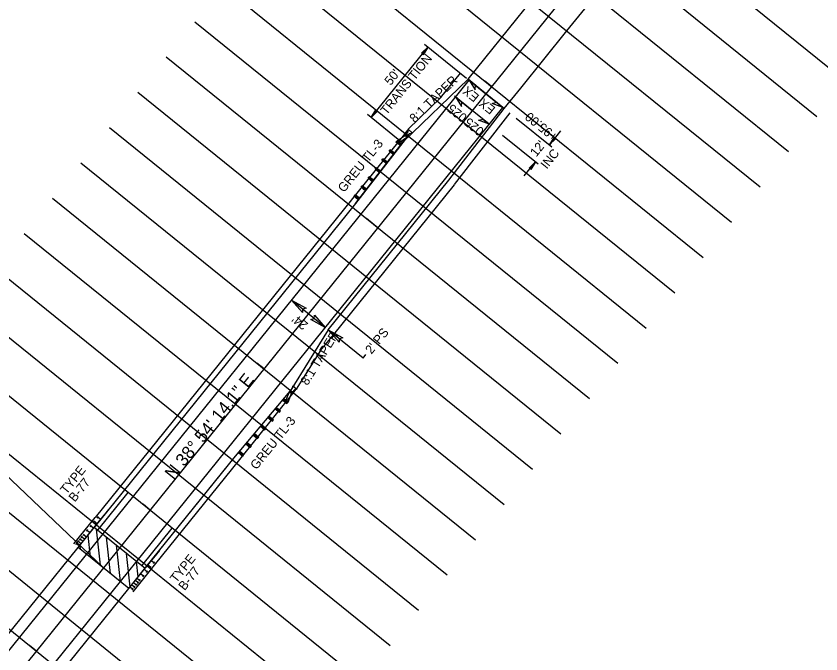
# Model space of a CAD drawing. Extents: x 2292992 to 2295123, y 892701 to 896230.
# Drawn here: x 2293899.6 to 2294343.7, y 893581.3 to 893933 of the extents above; entities that cross this region are included whole.
import ezdxf

# ---------------------------------------------------------------- set-up
doc = ezdxf.new("R2010")
doc.units = 0
for name, color, linetype in [('Default', 7, 'Continuous'), ('Prop Approach Slab', 7, 'Continuous'), ('Prop Approach Slab Hatching', 7, 'Continuous'), ('Prop Conc Shoulder Berm Gutter', 7, 'Continuous'), ('Prop Dimension', 7, 'Continuous'), ('Prop Dimension Text', 7, 'Continuous'), ('Prop EOT', 7, 'Continuous'), ('Prop Guardrail', 7, 'Continuous'), ('Prop Guardrail Anchor Unit CELL', 7, 'Continuous'), ('Prop Horizontal Alignment', 7, 'Continuous'), ('Prop Horizontal Alignment Direction Label', 7, 'Continuous'), ('Prop Horizontal Alignment Tick Large', 7, 'Continuous'), ('Prop Horizontal Alignment Tick Small', 7, 'Continuous'), ('Prop Paved Shoulder', 7, 'Continuous'), ('Prop Roadway Bridge', 7, 'Continuous'), ('Prop SBG', 7, 'Continuous'), ('Prop Structure Anchor Unit CELL', 7, 'Continuous'), ('Prop Superelevation  Arrow CELL', 7, 'Continuous'), ('Prop Superelevation Label', 7, 'Continuous'), ('Prop Terminator CELL', 7, 'Continuous'), ('Scratch_Level_0', 7, 'Continuous'), ('Scratch_Level_3', 7, 'Continuous'), ('Scratch_Level_4', 7, 'Continuous'), ('Scratch_Level_5', 7, 'Continuous'), ('Typical Terminator CELL', 7, 'Continuous')]:
    doc.layers.add(name, color=color, linetype=linetype)

# ---------------------------------------------------------------- blocks, each defined once
blk = doc.blocks.new('TERMINATOR')
at = {"layer": 'Typical Terminator CELL'}
blk.add_lwpolyline([(-0.469, 0.081), (0, 0), (-0.471, -0.083), (-0.411, 0)], close=True, dxfattribs=at)

msp = doc.modelspace()

# ---------------------------------------------------------------- linework, layer by layer
at = {"layer": 'Default'}
for p, q in [((2294158.83, 893890.22), (2294148.96, 893898.19)), ((2294151.29, 893880.88), (2294141.42, 893888.85)), ((2294158.83, 893890.22), (2294168.95, 893882.05))]:
    msp.add_line(p, q, dxfattribs=at)
at = {"layer": 'Prop Approach Slab'}
for p, q in [((2293933.81, 893640.05), (2293943.23, 893651.72)), ((2293970.72, 893628.47), (2293942.71, 893651.08)), ((2293961.82, 893617.44), (2293971.24, 893629.11))]:
    msp.add_line(p, q, dxfattribs=at)
at = {"layer": 'Prop Approach Slab Hatching'}
for p, q in [((2293946.08, 893630.14), (2293943.96, 893650.07)), ((2293940.58, 893634.58), (2293939.27, 893646.82)), ((2293951.59, 893625.7), (2293949.46, 893645.63)), ((2293935.08, 893639.03), (2293934.83, 893641.32)), ((2293957.09, 893621.26), (2293954.96, 893641.19)), ((2293962.44, 893618.21), (2293960.46, 893636.75)), ((2293966.88, 893623.71), (2293965.97, 893632.31))]:
    msp.add_line(p, q, dxfattribs=at)
at = {"layer": 'Prop Conc Shoulder Berm Gutter'}
for p, q in [((2293950.62, 893660.88), (2293943.23, 893651.74)), ((2293978.62, 893638.26), (2293971.24, 893629.12))]:
    msp.add_line(p, q, dxfattribs=at)
at = {"layer": 'Prop Dimension'}
for p, q in [((2294095.46, 893877.11), (2294126.86, 893916.02)), ((2294124.91, 893917.6), (2294148.18, 893898.82)), ((2294112.45, 893863.4), (2294093.5, 893878.69)), ((2294175.59, 893876.7), (2294195.14, 893860.92)), ((2294168.05, 893867.36), (2294187.6, 893851.58)), ((2294200.05, 893869.8), (2294193.81, 893862.07)), ((2294179.96, 893844.91), (2294186.19, 893852.64)), ((2294070.18, 893761.26), (2294051.5, 893776.33)), ((2294091.05, 893744.42), (2294071.74, 893760.01)), ((2294091.05, 893744.42), (2294092.62, 893746.37))]:
    msp.add_line(p, q, dxfattribs=at)
at = {"layer": 'Prop Dimension Text'}
msp.add_line((2293783.81, 893784.73), (2293947.82, 893628.75), dxfattribs=at)
at = {"layer": 'Prop EOT'}
for p, q in [((2293677.44, 893312.82), (2294149.49, 893897.76)), ((2294168.17, 893882.69), (2294149.49, 893897.76)), ((2293696.11, 893297.74), (2294168.17, 893882.69))]:
    msp.add_line(p, q, dxfattribs=at)
for points in [[(2294148.97, 893898.17), (2294158.28, 893909.61), (2294184.27, 893942.27), (2294211.74, 893976.09), (2294233.52, 894003.42)], [(2294168.97, 893882.04), (2294178.04, 893893.2), (2294203.54, 893924.89), (2294231.52, 893959.52), (2294253.69, 893987.15)]]:
    msp.add_lwpolyline(points, dxfattribs=at)
at = {"layer": 'Prop Guardrail'}
for p, q in [((2294086.89, 893829.74), (2293945.58, 893654.64)), ((2293973.6, 893632.03), (2294020.7, 893690.4))]:
    msp.add_line(p, q, dxfattribs=at)
at = {"layer": 'Prop Guardrail Anchor Unit CELL'}
for p, q in [((2294086.89, 893829.74), (2294115.51, 893866.7)), ((2294109.79, 893864.3), (2294114.02, 893867.22)), ((2294114.02, 893867.22), (2294114.63, 893868.01)), ((2294114.02, 893867.22), (2294114.33, 893867.62)), ((2294115.21, 893866.3), (2294114.02, 893867.22)), ((2294115.82, 893867.09), (2294114.02, 893867.22)), ((2294115.8, 893869.13), (2294114.52, 893867.53)), ((2294114.52, 893867.53), (2294115, 893867.15)), ((2294115.82, 893867.09), (2294114.63, 893868.01)), ((2294114.63, 893868.01), (2294115.21, 893866.3)), ((2294115, 893867.15), (2294115.47, 893866.77)), ((2294115.47, 893866.77), (2294116.76, 893868.37)), ((2294115.87, 893870.59), (2294115.8, 893869.13)), ((2294118.17, 893868.74), (2294115.87, 893870.59)), ((2294116.76, 893868.37), (2294118.17, 893868.74)), ((2294109.17, 893863.51), (2294109.79, 893864.3)), ((2294111.59, 893861.64), (2294109.17, 893863.51)), ((2294111, 893863.37), (2294109.17, 893863.51)), ((2294112.21, 893862.43), (2294109.79, 893864.3)), ((2294109.79, 893864.3), (2294110.38, 893862.58)), ((2294110.38, 893862.58), (2294111, 893863.37)), ((2294110.38, 893862.58), (2294112.21, 893862.43)), ((2294111, 893863.37), (2294115.21, 893866.3)), ((2294111.59, 893861.64), (2294111, 893863.37)), ((2294105.36, 893858.49), (2294105.98, 893859.28)), ((2294107.74, 893856.66), (2294105.36, 893858.49)), ((2294107.16, 893858.36), (2294105.36, 893858.49)), ((2294108.35, 893857.45), (2294105.98, 893859.28)), ((2294105.98, 893859.28), (2294106.55, 893857.57)), ((2294106.55, 893857.57), (2294107.16, 893858.36)), ((2294107.74, 893856.66), (2294107.16, 893858.36)), ((2294101.4, 893853.59), (2294102.01, 893854.39)), ((2294103.88, 893851.67), (2294101.4, 893853.59)), ((2294103.25, 893853.42), (2294101.4, 893853.59)), ((2294104.49, 893852.46), (2294102.01, 893854.39)), ((2294102.01, 893854.39), (2294102.64, 893852.63)), ((2294102.64, 893852.63), (2294103.25, 893853.42)), ((2294103.88, 893851.67), (2294103.25, 893853.42)), ((2294106.55, 893857.57), (2294108.35, 893857.45)), ((2294097.62, 893848.55), (2294098.23, 893849.34)), ((2294100.63, 893847.48), (2294098.23, 893849.34)), ((2294098.23, 893849.34), (2294098.82, 893847.62)), ((2294102.64, 893852.63), (2294104.49, 893852.46)), ((2294100.02, 893846.69), (2294097.62, 893848.55)), ((2294099.43, 893848.41), (2294097.62, 893848.55)), ((2294098.82, 893847.62), (2294099.43, 893848.41)), ((2294098.82, 893847.62), (2294100.63, 893847.48)), ((2294100.02, 893846.69), (2294099.43, 893848.41)), ((2294100.02, 893846.69), (2294100.63, 893847.48)), ((2294093.75, 893843.58), (2294094.36, 893844.37)), ((2294096.16, 893841.71), (2294093.75, 893843.58)), ((2294095.57, 893843.43), (2294093.75, 893843.58)), ((2294096.77, 893842.5), (2294094.36, 893844.37)), ((2294094.36, 893844.37), (2294094.96, 893842.64)), ((2294094.96, 893842.64), (2294095.57, 893843.43)), ((2294094.96, 893842.64), (2294096.77, 893842.5)), ((2294096.16, 893841.71), (2294095.57, 893843.43)), ((2294089.89, 893838.6), (2294090.5, 893839.39)), ((2294092.3, 893836.73), (2294089.89, 893838.6)), ((2294091.71, 893838.45), (2294089.89, 893838.6)), ((2294092.92, 893837.52), (2294090.5, 893839.39)), ((2294090.5, 893839.39), (2294091.1, 893837.66)), ((2294091.1, 893837.66), (2294091.71, 893838.45)), ((2294091.1, 893837.66), (2294092.92, 893837.52)), ((2294092.3, 893836.73), (2294091.71, 893838.45)), ((2294086.07, 893833.58), (2294086.69, 893834.37)), ((2294088.44, 893831.75), (2294086.07, 893833.58)), ((2294087.87, 893833.46), (2294086.07, 893833.58)), ((2294089.06, 893832.54), (2294086.69, 893834.37)), ((2294086.69, 893834.37), (2294087.26, 893832.67)), ((2294087.26, 893832.67), (2294087.87, 893833.46)), ((2294087.26, 893832.67), (2294089.06, 893832.54)), ((2294089.06, 893832.54), (2294087.87, 893833.46)), ((2294087.87, 893833.46), (2294088.44, 893831.75)), ((2294088.44, 893831.75), (2294089.06, 893832.54)), ((2294052.15, 893727.75), (2294052.22, 893729.21)), ((2294052.22, 893729.21), (2294054.51, 893727.36)), ((2294020.7, 893690.4), (2294050.78, 893726.19)), ((2294048.48, 893721.07), (2294050.46, 893725.8)), ((2294049.65, 893720.08), (2294051.61, 893724.84)), ((2294050.46, 893725.8), (2294051.61, 893724.84)), ((2294052.25, 893725.6), (2294050.46, 893725.8)), ((2294050.86, 893726.16), (2294052.15, 893727.75)), ((2294051.34, 893725.78), (2294050.86, 893726.16)), ((2294051.1, 893726.57), (2294052.25, 893725.6)), ((2294051.1, 893726.57), (2294051.61, 893724.84)), ((2294051.81, 893725.39), (2294051.34, 893725.78)), ((2294051.61, 893724.84), (2294052.25, 893725.6)), ((2294051.61, 893724.84), (2294051.93, 893725.22)), ((2294053.1, 893726.98), (2294051.81, 893725.39)), ((2294054.51, 893727.36), (2294053.1, 893726.98)), ((2294046.66, 893721.29), (2294049.01, 893719.31)), ((2294046.66, 893721.29), (2294048.48, 893721.07)), ((2294047.31, 893722.05), (2294049.65, 893720.08)), ((2294047.84, 893720.3), (2294047.31, 893722.05)), ((2294047.84, 893720.3), (2294048.48, 893721.07)), ((2294049.65, 893720.08), (2294047.84, 893720.3)), ((2294048.48, 893721.07), (2294049.01, 893719.31)), ((2294042.61, 893716.46), (2294044.91, 893714.53)), ((2294042.61, 893716.46), (2294044.4, 893716.26)), ((2294043.25, 893717.23), (2294045.55, 893715.3)), ((2294043.76, 893715.5), (2294043.25, 893717.23)), ((2294043.76, 893715.5), (2294044.4, 893716.26)), ((2294044.4, 893716.26), (2294044.91, 893714.53)), ((2294049.01, 893719.31), (2294049.65, 893720.08)), ((2294038.55, 893711.64), (2294040.96, 893709.62)), ((2294038.55, 893711.64), (2294040.4, 893711.39)), ((2294039.2, 893712.4), (2294041.6, 893710.38)), ((2294039.75, 893710.63), (2294039.2, 893712.4)), ((2294039.75, 893710.63), (2294040.4, 893711.39)), ((2294040.4, 893711.39), (2294040.96, 893709.62)), ((2294045.55, 893715.3), (2294043.76, 893715.5)), ((2294044.91, 893714.53), (2294045.55, 893715.3)), ((2294034.5, 893706.81), (2294035.14, 893707.58)), ((2294034.5, 893706.81), (2294036.82, 893704.86)), ((2294034.5, 893706.81), (2294036.31, 893706.6)), ((2294035.14, 893707.58), (2294037.47, 893705.63)), ((2294035.66, 893705.84), (2294035.14, 893707.58)), ((2294041.6, 893710.38), (2294039.75, 893710.63)), ((2294040.96, 893709.62), (2294041.6, 893710.38)), ((2294031.09, 893702.76), (2294033.42, 893700.8)), ((2294031.61, 893701.01), (2294031.09, 893702.76)), ((2294035.66, 893705.84), (2294036.31, 893706.6)), ((2294037.47, 893705.63), (2294035.66, 893705.84)), ((2294036.31, 893706.6), (2294036.82, 893704.86)), ((2294036.82, 893704.86), (2294037.47, 893705.63)), ((2294027.03, 893697.93), (2294029.37, 893695.97)), ((2294027.56, 893696.19), (2294027.03, 893697.93)), ((2294030.45, 893701.99), (2294032.78, 893700.03)), ((2294030.45, 893701.99), (2294032.26, 893701.78)), ((2294031.61, 893701.01), (2294032.26, 893701.78)), ((2294033.42, 893700.8), (2294031.61, 893701.01)), ((2294032.26, 893701.78), (2294032.78, 893700.03)), ((2294032.78, 893700.03), (2294033.42, 893700.8)), ((2294026.39, 893697.17), (2294028.73, 893695.2)), ((2294026.39, 893697.17), (2294028.2, 893696.95)), ((2294027.56, 893696.19), (2294028.2, 893696.95)), ((2294029.37, 893695.97), (2294027.56, 893696.19)), ((2294028.2, 893696.95), (2294028.73, 893695.2)), ((2294028.73, 893695.2), (2294029.37, 893695.97)), ((2294022.34, 893692.34), (2294022.98, 893693.11)), ((2294022.34, 893692.34), (2294024.63, 893690.41)), ((2294024.13, 893692.14), (2294022.34, 893692.34)), ((2294022.98, 893693.11), (2294025.28, 893691.18)), ((2294022.98, 893693.11), (2294024.13, 893692.14)), ((2294023.48, 893691.38), (2294022.98, 893693.11)), ((2294023.48, 893691.38), (2294024.13, 893692.14)), ((2294025.28, 893691.18), (2294023.48, 893691.38)), ((2294024.13, 893692.14), (2294024.63, 893690.41)), ((2294024.63, 893690.41), (2294025.28, 893691.18))]:
    msp.add_line(p, q, dxfattribs=at)
at = {"layer": 'Prop Horizontal Alignment'}
msp.add_line((2293686.78, 893305.28), (2294292.7, 894056.1), dxfattribs=at)
at = {"layer": 'Prop Horizontal Alignment Tick Large'}
msp.add_line((2294099.17, 893816.29), (2294092.94, 893821.32), dxfattribs=at)
at = {"layer": 'Prop Horizontal Alignment Tick Small'}
for p, q in [((2294161.97, 893894.11), (2294158.08, 893897.25)), ((2294036.37, 893738.47), (2294032.48, 893741.61)), ((2293973.56, 893660.65), (2293969.67, 893663.79)), ((2293910.76, 893582.83), (2293906.87, 893585.97))]:
    msp.add_line(p, q, dxfattribs=at)
at = {"layer": 'Prop Paved Shoulder'}
for p, q in [((2294113.14, 893863.64), (2294148.96, 893898.19)), ((2294148.96, 893898.19), (2294149.49, 893897.76)), ((2294138.32, 893842.52), (2294168.95, 893882.05)), ((2294168.95, 893882.05), (2294168.17, 893882.69)), ((2294086.89, 893829.74), (2294113.14, 893863.64)), ((2294071.74, 893760.01), (2294138.32, 893842.52)), ((2294086.9, 893829.73), (2293945.59, 893654.64)), ((2294071.74, 893760.01), (2294050.78, 893726.19)), ((2294020.7, 893690.4), (2294050.78, 893726.19)), ((2293971.24, 893629.12), (2294020.69, 893690.4)), ((2293943.24, 893651.72), (2293945.59, 893654.64))]:
    msp.add_line(p, q, dxfattribs=at)
at = {"layer": 'Prop Roadway Bridge'}
for p, q in [((2293801.93, 893476.63), (2293933.81, 893640.05)), ((2293933.18, 893639.27), (2293933.18, 893639.27)), ((2293961.82, 893617.44), (2293933.81, 893640.05)), ((2293829.94, 893454.02), (2293961.82, 893617.44))]:
    msp.add_line(p, q, dxfattribs=at)
at = {"layer": 'Prop SBG'}
for p, q in [((2293961.17, 893670.21), (2293944.53, 893649.61)), ((2293968.9, 893629.94), (2293985.6, 893650.62))]:
    msp.add_line(p, q, dxfattribs=at)
at = {"layer": 'Prop Structure Anchor Unit CELL'}
for p, q in [((2293933.81, 893640.05), (2293948.17, 893657.85)), ((2293942.33, 893653.8), (2293943.05, 893654.69)), ((2293944.25, 893652.99), (2293942.69, 893654.24)), ((2293944.3, 893656.23), (2293945.02, 893657.12)), ((2293946.21, 893655.42), (2293944.66, 893656.68)), ((2293938.41, 893648.93), (2293939.13, 893649.83)), ((2293940.32, 893648.12), (2293938.77, 893649.38)), ((2293940.37, 893651.37), (2293941.09, 893652.26)), ((2293942.29, 893650.56), (2293940.73, 893651.81)), ((2293934.48, 893644.07), (2293935.2, 893644.96)), ((2293935.46, 893645.29), (2293936.18, 893646.18)), ((2293937.38, 893644.48), (2293935.82, 893645.73)), ((2293936.45, 893646.5), (2293937.16, 893647.39)), ((2293938.36, 893645.69), (2293936.81, 893646.95)), ((2293932.52, 893641.64), (2293933.24, 893642.53)), ((2293934.44, 893640.83), (2293932.88, 893642.08)), ((2293933.5, 893642.85), (2293934.22, 893643.75)), ((2293935.42, 893642.04), (2293933.86, 893643.3)), ((2293936.4, 893643.26), (2293934.84, 893644.52)), ((2293961.82, 893617.44), (2293976.19, 893635.24)), ((2293974.23, 893632.81), (2293975.78, 893631.56)), ((2293975.42, 893631.11), (2293976.14, 893632)), ((2293970.3, 893627.95), (2293971.86, 893626.69)), ((2293971.5, 893626.25), (2293972.22, 893627.14)), ((2293972.26, 893630.38), (2293973.82, 893629.12)), ((2293973.46, 893628.68), (2293974.18, 893629.57)), ((2293966.38, 893623.08), (2293967.93, 893621.83)), ((2293968.34, 893625.52), (2293969.9, 893624.26)), ((2293969.54, 893623.81), (2293970.26, 893624.71)), ((2293962.45, 893618.22), (2293964.01, 893616.96)), ((2293963.43, 893619.44), (2293964.99, 893618.18)), ((2293964.41, 893620.65), (2293965.97, 893619.4)), ((2293964.63, 893617.73), (2293965.35, 893618.63)), ((2293965.4, 893621.87), (2293966.95, 893620.61)), ((2293965.61, 893618.95), (2293966.33, 893619.84)), ((2293966.59, 893620.17), (2293967.31, 893621.06)), ((2293967.57, 893621.38), (2293968.29, 893622.27)), ((2293963.65, 893616.52), (2293964.37, 893617.41))]:
    msp.add_line(p, q, dxfattribs=at)
at = {"layer": 'Prop Superelevation  Arrow CELL'}
for p, q in [((2294149.49, 893897.76), (2294158.83, 893890.22)), ((2294168.17, 893882.69), (2294158.83, 893890.22)), ((2294141.95, 893888.42), (2294151.29, 893880.88)), ((2294160.63, 893873.35), (2294151.29, 893880.88))]:
    msp.add_line(p, q, dxfattribs=at)
for points in [[(2294149.49, 893897.76), (2294152.9, 893892.43), (2294153.09, 893894.85)], [(2294141.95, 893888.42), (2294145.37, 893883.09), (2294145.55, 893885.51)], [(2294168.17, 893882.69), (2294162.24, 893884.9), (2294164.57, 893885.59)], [(2294160.63, 893873.35), (2294154.71, 893875.56), (2294157.03, 893876.25)]]:
    msp.add_lwpolyline(points, close=True, dxfattribs=at)
at = {"layer": 'Prop Terminator CELL'}
for points in [[(2294057.53, 893769.48), (2294051.5, 893776.33), (2294059.55, 893771.9), (2294057.65, 893771.37)], [(2294064.15, 893768.12), (2294070.18, 893761.26), (2294062.13, 893765.7), (2294064.03, 893766.22)], [(2294077.77, 893753.15), (2294071.74, 893760.01), (2294079.78, 893755.57), (2294077.88, 893755.05)]]:
    msp.add_lwpolyline(points, close=True, dxfattribs=at)
at = {"layer": 'Scratch_Level_0'}
for p, q in [((2294133.8, 893887.87), (2294144.82, 893901.53)), ((2294133.8, 893887.87), (2294115.87, 893870.59)), ((2294141.49, 893840.07), (2294172.11, 893879.6)), ((2294113.93, 893867.92), (2294084.51, 893831.58)), ((2294113.93, 893867.92), (2294115.82, 893870.26)), ((2294074.85, 893757.49), (2294141.44, 893840.01)), ((2294084.55, 893831.63), (2293943.24, 893656.53)), ((2294067.61, 893748.53), (2294074.85, 893757.49)), ((2294067.61, 893748.53), (2294054.19, 893727.24)), ((2294023, 893688.46), (2294052.31, 893724.9)), ((2294052.31, 893724.9), (2294054.19, 893727.24)), ((2293975.94, 893630.14), (2294023.04, 893688.51)), ((2293931.47, 893641.94), (2293943.24, 893656.53)), ((2293964.17, 893615.55), (2293975.94, 893630.14))]:
    msp.add_line(p, q, dxfattribs=at)
at = {"layer": 'Scratch_Level_3'}
msp.add_line((2293686.78, 893305.28), (2294292.7, 894056.1), dxfattribs=at)
at = {"layer": 'Scratch_Level_4'}
for p, q in [((2294123.74, 894085.59), (2294357.2, 893897.18)), ((2294108.04, 894066.13), (2294341.5, 893877.73)), ((2294092.34, 894046.68), (2294325.8, 893858.27)), ((2294076.64, 894027.22), (2294310.1, 893838.82)), ((2294060.94, 894007.77), (2294294.4, 893819.36)), ((2294045.24, 893988.31), (2294278.7, 893799.91)), ((2294029.54, 893968.86), (2294263, 893780.45)), ((2294013.84, 893949.4), (2294247.3, 893761)), ((2293998.14, 893929.95), (2294231.6, 893741.54)), ((2293982.44, 893910.49), (2294215.9, 893722.09)), ((2293966.74, 893891.04), (2294200.2, 893702.63)), ((2293951.04, 893871.58), (2294184.5, 893683.18)), ((2293935.34, 893852.13), (2294168.8, 893663.72)), ((2293919.64, 893832.67), (2294153.1, 893644.27)), ((2293903.94, 893813.22), (2294137.4, 893624.81)), ((2293888.24, 893793.76), (2294121.7, 893605.36)), ((2293872.54, 893774.31), (2294106, 893585.9)), ((2293856.83, 893754.85), (2294090.29, 893566.45)), ((2293841.13, 893735.4), (2294074.59, 893546.99)), ((2293825.43, 893715.94), (2294058.89, 893527.54)), ((2293809.73, 893696.49), (2294043.19, 893508.08)), ((2293794.03, 893677.03), (2294027.49, 893488.63))]:
    msp.add_line(p, q, dxfattribs=at)
at = {"layer": 'Scratch_Level_5'}
for p, q in [((2294115.51, 893866.7), (2294086.88, 893829.74)), ((2294086.88, 893829.74), (2293945.58, 893654.65)), ((2294020.71, 893690.39), (2294050.79, 893726.18)), ((2293973.61, 893632.03), (2294020.71, 893690.39)), ((2293933.8, 893640.06), (2293945.58, 893654.65)), ((2293961.83, 893617.44), (2293973.61, 893632.03))]:
    msp.add_line(p, q, dxfattribs=at)

# ---------------------------------------------------------------- block references
at = {"layer": 'Prop Dimension Text'}
for p, xscale, yscale, rotation in [((2294126.86, 893916.02), 10.604453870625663, 7.610350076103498, 51.09608270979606), ((2294095.46, 893877.11), 10.604453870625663, 7.610350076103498, -128.90391729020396), ((2294193.77, 893862.02), 10.604453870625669, -7.6103500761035, -128.94654212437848), ((2294186.23, 893852.69), 10.604453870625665, 7.6103500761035, 51.09608271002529)]:
    msp.add_blockref('TERMINATOR', p, dxfattribs=dict(at, xscale=xscale, yscale=yscale, rotation=rotation))

# ---------------------------------------------------------------- texts
for s, rotation, p in [('TRANSITION', 51.0961, (2294104.04, 893878.13)), ("50'", 51.0961, (2294106.24, 893894.44)), ('8:1 TAPER', 43.971, (2294119.53, 893873.88)), ('+95.00', 141.0961, (2294199.07, 893867.44)), ("12'", 51.0961, (2294186.61, 893855.06)), ('INC', 51.0961, (2294192.43, 893848.3)), ("24'", 141.0961, (2294061.09, 893763.38)), ("2' PS", 51.0748, (2294095.64, 893746.23)), ('8:1 TAPER', 58.2212, (2294060.31, 893728.94))]:
    msp.add_text(s, height=5, rotation=rotation, dxfattribs=at).set_placement(p)
at = {"layer": 'Prop Guardrail Anchor Unit CELL'}
for p in [(2294080.51, 893835.42), (2294032.2, 893682.53)]:
    msp.add_text('GREU TL-3', height=5, rotation=51.0961, dxfattribs=at).set_placement(p)
at = {"layer": 'Prop Horizontal Alignment Direction Label'}
msp.add_text('N 38%%d 54\' 14.1" E', height=7, rotation=51.0961, dxfattribs=at).set_placement((2293986.44, 893676.91))
at = {"layer": 'Prop Structure Anchor Unit CELL'}
for s, p in [('TYPE', (2293927.34, 893668.95)), ('B-77', (2293931.96, 893664.72)), ('TYPE', (2293987.94, 893620.11)), ('B-77', (2293992.55, 893615.88))]:
    msp.add_text(s, height=5, rotation=51.0961, dxfattribs=at).set_placement(p)
at = {"layer": 'Prop Superelevation Label'}
for s, p in [('EX', (2294155.54, 893889.09)), ('EX', (2294164.45, 893882.31)), ('025', (2294148.84, 893877.9)), ('025', (2294158.18, 893870.36))]:
    msp.add_text(s, height=5, rotation=141.0961, dxfattribs=at).set_placement(p)

doc.saveas('drawing.dxf')
